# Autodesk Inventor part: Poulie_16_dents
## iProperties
Created: 2011-01
Part Number: Poulie_16_dents
Document SubType Name: Modeling
Designer: eric
Density: 1 g/cm^3
Mass: 2.61218 g
Surface Area: 20.1218 cm^2
Volume: 2.61218 cm^3
Author: eric
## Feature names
1. Base1
